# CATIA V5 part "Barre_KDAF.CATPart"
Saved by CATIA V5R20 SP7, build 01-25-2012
Part number: Barre_KDAF
Bounding box of the stored display mesh (mm): x -155 to 155, y 25 to 35, z 0 to 5
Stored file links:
  D:\IFMA\COURS\2A\projet balance IAO\catia\Barre_KDAF.CATPart
  D:\IFMA\COURS\2A\projet balance IAO\catia\Ass_projet_balance.CATProduct
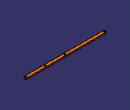
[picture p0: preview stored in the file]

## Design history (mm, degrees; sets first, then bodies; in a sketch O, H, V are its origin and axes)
Set1
  Plane1 "Plan.KDAF": linked copy from another document
  Point1 "Point.F": linked copy from another document
  Point2 "Point.K": linked copy from another document
  Point3 "Point.D": linked copy from another document
  Point4 "Point.A": linked copy from another document
Body1 (main body)
  Sketch1 on Plane1, origin (0, 0, 0), H (1, 0, 0), V (0, 1, 0)
    arc A1 centre (150, 30) radius 5 from (150, 25) to (150, 35) ccw
    point P1 (150, 30)
    arc A2 centre (-150, 30) radius 5 from (-150, 35) to (-150, 25) ccw
    point P4 (-150, 30)
    line L1 (150, 35) -> (-150, 35)
    line L2 (150, 25) -> (-150, 25)
    reference projected point E1 (150, 30) from Point1
    reference projected point E2 (-150, 30) from Point2
    distance L1 L2 = 10
    horizontal: L1 H
    tangency: L2 A1, A2 L1, A1 L1, A2 L2
    coincidence: P1 E1, P4 E2
  Pad1: profile Sketch1, direction (0, 0, 1), length 5
  Sketch2 on start face of Pad1, origin (0, 0, 0), H (1, 0, 0), V (0, -1, 0)
    circle A1 centre (-150, -30) radius 2.5
    point P1 (-150, -30)
    circle A2 centre (0, -30) radius 2.5
    point P2 (0, -30)
    circle A3 centre (75, -30) radius 2.5
    point P3 (75, -30)
    circle A4 centre (150, -30) radius 2.5
    point P4 (150, -30)
    reference projected point E1 (-150, -30) from Point2
    reference projected point E2 (0, -30) from Point3
    reference projected point E3 (75, -30) from Point4
    reference projected point E4 (150, -30) from Point1
    radius A4 = 2.5
    radius A1 = 2.5
    radius A2 = 2.5
    radius A3 = 2.5
    coincidence: P1 E1, P2 E2, P3 E3, P4 E4
  Pocket1: profile Sketch2, direction (0, 0, 1), through (limit type 6)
